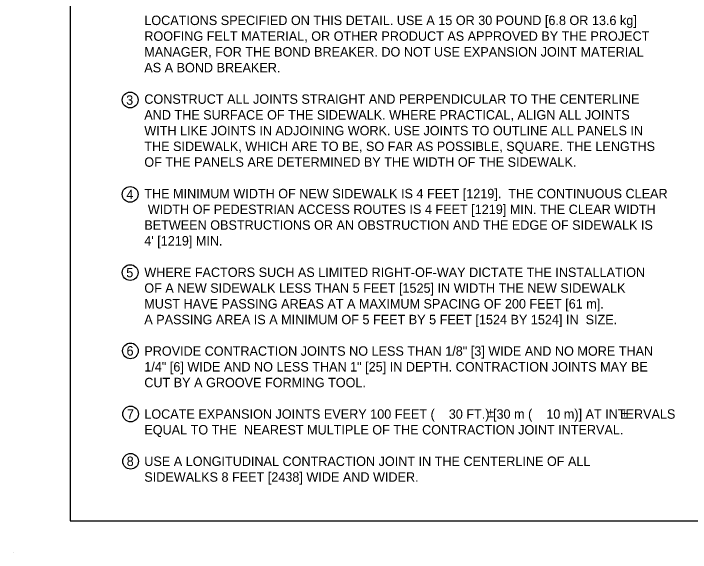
# Model space of a CAD drawing. Extents: x 49987.9 to 50021, y 49987.6 to 50011.4.
# Drawn here: x 49999.977 to 50004.279, y 49999.862 to 50003.285 of the extents above; entities that cross this region are included whole.
import ezdxf

# ---------------------------------------------------------------- set-up
doc = ezdxf.new("R2010")
doc.units = 0
for name, color, linetype in [('Level 1', 7, 'Continuous'), ('Level 2', 7, 'Continuous'), ('Level 3', 7, 'Continuous')]:
    doc.layers.add(name, color=color, linetype=linetype)

msp = doc.modelspace()

# ---------------------------------------------------------------- linework, layer by layer
at = {"layer": 'Level 1'}
msp.add_line((49999.9766, 49999.8624), (49999.9766, 49999.8624), dxfattribs=at)
msp.add_lwpolyline([(50008.6146, 50011.2628), (50000.3356, 50011.2628), (50000.3356, 50000.0624), (50008.6146, 50000.0624)], close=True, dxfattribs=at)
at = {"layer": 'Level 2'}
for centre in [(50000.7177, 50002.7354), (50000.7177, 50002.1363), (50000.7177, 50001.6397), (50000.7193, 50001.1423), (50000.7205, 50000.7414), (50000.7205, 50000.4414)]:
    msp.add_circle(centre, 0.05, dxfattribs=at)

# ---------------------------------------------------------------- texts
for s, p in [('LOCATIONS SPECIFIED ON THIS DETAIL. USE A 15 OR 30 POUND [6.8 OR 13.6 kg]', (50000.8077, 50003.2115)), ('ROOFING FELT MATERIAL, OR OTHER PRODUCT AS APPROVED BY THE PROJECT', (50000.8077, 50003.1115)), ('MANAGER, FOR THE BOND BREAKER. DO NOT USE EXPANSION JOINT MATERIAL', (50000.8077, 50003.0115)), ('AS A BOND BREAKER.', (50000.8077, 50002.9115)), ('3', (50000.6925, 50002.7054)), ('CONSTRUCT ALL JOINTS STRAIGHT AND PERPENDICULAR TO THE CENTERLINE', (50000.8077, 50002.7115)), ('AND THE SURFACE OF THE SIDEWALK. WHERE PRACTICAL, ALIGN ALL JOINTS', (50000.8077, 50002.6115)), ('WITH LIKE JOINTS IN ADJOINING WORK. USE JOINTS TO OUTLINE ALL PANELS IN', (50000.8077, 50002.5115)), ('THE SIDEWALK, WHICH ARE TO BE, SO FAR AS POSSIBLE, SQUARE. THE LENGTHS', (50000.8077, 50002.4115)), ('OF THE PANELS ARE DETERMINED BY THE WIDTH OF THE SIDEWALK.', (50000.8077, 50002.3115)), ('4', (50000.6938, 50002.1063)), ('THE MINIMUM WIDTH OF NEW SIDEWALK IS 4 FEET [1219].  THE CONTINUOUS CLEAR', (50000.8077, 50002.1115)), (' WIDTH OF PEDESTRIAN ACCESS ROUTES IS 4 FEET [1219] MIN. THE CLEAR WIDTH', (50000.8077, 50002.0115)), ('BETWEEN OBSTRUCTIONS OR AN OBSTRUCTION AND THE EDGE OF SIDEWALK IS', (50000.8077, 50001.9115)), ("4' [1219] MIN.", (50000.8077, 50001.8115)), ('5', (50000.6928, 50001.6097)), ('WHERE FACTORS SUCH AS LIMITED RIGHT-OF-WAY DICTATE THE INSTALLATION', (50000.8077, 50001.6115)), ('OF A NEW SIDEWALK LESS THAN 5 FEET [1525] IN WIDTH THE NEW SIDEWALK', (50000.8077, 50001.5115)), ('MUST HAVE PASSING AREAS AT A MAXIMUM SPACING OF 200 FEET [61 m].', (50000.8077, 50001.4115)), ('A PASSING AREA IS A MINIMUM OF 5 FEET BY 5 FEET [1524 BY 1524] IN  SIZE.', (50000.8077, 50001.3115)), ('6', (50000.6947, 50001.1123)), ('PROVIDE CONTRACTION JOINTS NO LESS THAN 1/8" [3] WIDE AND NO MORE THAN', (50000.8077, 50001.1115)), ('1/4" [6] WIDE AND NO LESS THAN 1" [25] IN DEPTH. CONTRACTION JOINTS MAY BE', (50000.8077, 50001.0115)), ('CUT BY A GROOVE FORMING TOOL.', (50000.8077, 50000.9115)), ('7', (50000.6969, 50000.7114)), ('LOCATE EXPANSION JOINTS EVERY 100 FEET (    30 FT.) [30 m (    10 m)] AT INTERVALS', (50000.8077, 50000.7115)), ('EQUAL TO THE  NEAREST MULTIPLE OF THE CONTRACTION JOINT INTERVAL.', (50000.8077, 50000.6115)), ('8', (50000.6957, 50000.4114)), ('USE A LONGITUDINAL CONTRACTION JOINT IN THE CENTERLINE OF ALL', (50000.8077, 50000.4115)), ('SIDEWALKS 8 FEET [2438] WIDE AND WIDER.', (50000.8077, 50000.3115))]:
    msp.add_text(s, height=0.06, dxfattribs=at).set_placement(p)
at = {"layer": 'Level 3'}
for p in [(50002.9867, 50000.7214), (50003.8363, 50000.7119)]:
    msp.add_text('±', height=0.06, dxfattribs=at).set_placement(p)

doc.saveas('drawing.dxf')
